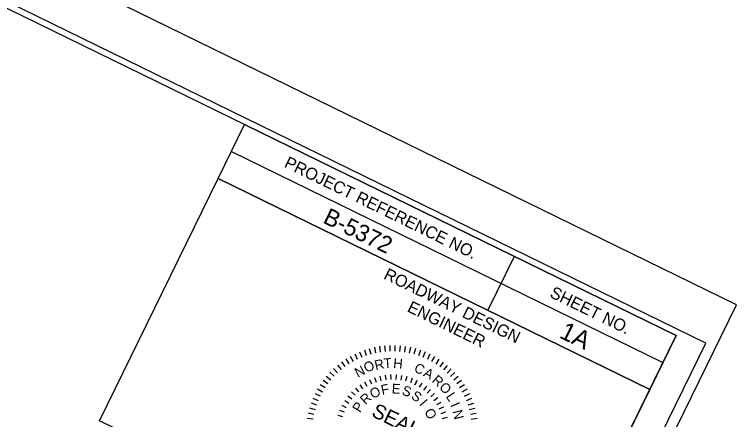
# Model space of a CAD drawing. Extents: x 1517888 to 1526099, y 633375 to 640181.
# Drawn here: x 1522517 to 1523118, y 635247 to 635585 of the extents above; entities that cross this region are included whole.
import ezdxf

# ---------------------------------------------------------------- set-up
doc = ezdxf.new("R2010")
doc.units = 0
for name, color, linetype in [('Default', 7, 'Continuous'), ('Sheet Cutting Line CELL', 7, 'Continuous'), ('Sheet Data Field CELL', 7, 'Continuous'), ('Sheet Plan CELL', 7, 'Continuous'), ('Sheet Plot Border Inside CELL', 7, 'Continuous'), ('Sheet Plot Border Outside CELL', 7, 'Continuous')]:
    doc.layers.add(name, color=color, linetype=linetype)

msp = doc.modelspace()

# ---------------------------------------------------------------- linework, layer by layer
at = {"layer": 'Default'}
for p, q in [((1522816.43, 635307.4), (1522817.44, 635302.63)), ((1522820.68, 635308.16), (1522821.4, 635303.34)), ((1522824.97, 635308.68), (1522825.4, 635303.82)), ((1522829.29, 635308.93), (1522829.42, 635304.05)), ((1522833.61, 635308.91), (1522833.44, 635304.04)), ((1522837.92, 635308.64), (1522837.47, 635303.78)), ((1522842.21, 635308.11), (1522841.46, 635303.29)), ((1522846.46, 635307.32), (1522845.42, 635302.56)), ((1522800.11, 635301.81), (1522802.24, 635297.43)), ((1522804.06, 635303.58), (1522805.91, 635299.07)), ((1522808.1, 635305.1), (1522809.68, 635300.49)), ((1522812.23, 635306.37), (1522813.53, 635301.67)), ((1522850.65, 635306.27), (1522849.33, 635301.58)), ((1522854.77, 635304.97), (1522853.17, 635300.37)), ((1522858.8, 635303.43), (1522856.92, 635298.93)), ((1522862.74, 635301.65), (1522860.6, 635297.27)), ((1522789.01, 635295.15), (1522791.9, 635291.21)), ((1522792.58, 635297.6), (1522795.21, 635293.49)), ((1522796.28, 635299.82), (1522798.66, 635295.57)), ((1522866.56, 635299.63), (1522864.16, 635295.39)), ((1522870.25, 635297.38), (1522867.6, 635293.3)), ((1522873.81, 635294.92), (1522870.91, 635291)), ((1522782.36, 635289.64), (1522785.7, 635286.07)), ((1522785.61, 635292.49), (1522788.72, 635288.74)), ((1522877.2, 635292.25), (1522874.07, 635288.51)), ((1522880.43, 635289.37), (1522877.08, 635285.82)), ((1522776.42, 635283.36), (1522780.17, 635280.23)), ((1522779.3, 635286.59), (1522782.85, 635283.24)), ((1522820.93, 635283.42), (1522821.82, 635279.45)), ((1522825.41, 635284.2), (1522825.91, 635280.16)), ((1522829.96, 635284.54), (1522830.07, 635280.49)), ((1522834.51, 635284.45), (1522834.23, 635280.4)), ((1522839.04, 635283.92), (1522838.36, 635279.91)), ((1522843.49, 635282.95), (1522842.43, 635279.02)), ((1522883.47, 635286.31), (1522879.91, 635282.98)), ((1522886.32, 635283.06), (1522882.58, 635279.95)), ((1522773.75, 635279.97), (1522777.67, 635277.07)), ((1522808.2, 635278.55), (1522810.19, 635275)), ((1522812.28, 635280.58), (1522813.92, 635276.86)), ((1522816.54, 635282.2), (1522817.81, 635278.34)), ((1522847.82, 635281.55), (1522846.4, 635277.75)), ((1522852.01, 635279.75), (1522850.22, 635276.1)), ((1522850.22, 635276.1), (1522852.01, 635279.75)), ((1522856, 635277.55), (1522853.87, 635274.09)), ((1522888.99, 635279.66), (1522885.05, 635276.78)), ((1522769.05, 635272.73), (1522773.29, 635270.32)), ((1522771.29, 635276.42), (1522775.38, 635273.76)), ((1522800.73, 635273.35), (1522803.36, 635270.25)), ((1522804.35, 635276.13), (1522806.66, 635272.79)), ((1522859.75, 635274.98), (1522857.3, 635271.74)), ((1522863.25, 635272.05), (1522860.49, 635269.06)), ((1522891.43, 635276.09), (1522887.33, 635273.46)), ((1522893.66, 635272.39), (1522889.4, 635270.01)), ((1522765.24, 635264.97), (1522769.74, 635263.09)), ((1522767.03, 635268.9), (1522771.41, 635266.76)), ((1522794.4, 635266.82), (1522797.58, 635264.28)), ((1522797.41, 635270.23), (1522800.33, 635267.41)), ((1522866.44, 635268.8), (1522863.41, 635266.09)), ((1522869.3, 635265.26), (1522866.03, 635262.86)), ((1522895.65, 635268.56), (1522891.27, 635266.44)), ((1522763.7, 635260.93), (1522768.3, 635259.33)), ((1522789.44, 635259.19), (1522793.04, 635257.31)), ((1522791.73, 635263.12), (1522795.14, 635260.91)), ((1522871.82, 635261.46), (1522868.32, 635259.38)), ((1522897.42, 635264.61), (1522892.91, 635262.76)), ((1522898.93, 635260.57), (1522894.32, 635258.99)), ((1522761.36, 635252.62), (1522766.12, 635251.58)), ((1522762.4, 635256.81), (1522767.09, 635255.49)), ((1522787.53, 635255.05), (1522791.3, 635253.53)), ((1522873.95, 635257.43), (1522870.26, 635255.7)), ((1522875.67, 635253.21), (1522871.84, 635251.85)), ((1522900.21, 635256.44), (1522895.51, 635255.15)), ((1522760.56, 635248.37), (1522765.39, 635247.62)), ((1522786.04, 635250.75), (1522789.93, 635249.6)), ((1522876.99, 635248.85), (1522873.05, 635247.87)), ((1522901.23, 635252.24), (1522896.47, 635251.23)), ((1522902, 635247.99), (1522897.18, 635247.27))]:
    msp.add_line(p, q, dxfattribs=at)
at = {"layer": 'Sheet Cutting Line CELL'}
msp.add_line((1523118.12, 635342.8), (1520093.48, 636822.08), dxfattribs=at)
at = {"layer": 'Sheet Plan CELL'}
for p, q in [((1522697.36, 635470.55), (1523056.78, 635294.76)), ((1522686.38, 635448.09), (1523045.79, 635272.3)), ((1522686.38, 635448.09), (1523045.79, 635272.3)), ((1522933.01, 635383.12), (1522911.04, 635338.21))]:
    msp.add_line(p, q, dxfattribs=at)
for points in [[(1523067.8, 635317.31), (1520372.85, 636635.35), (1519450.22, 634748.89), (1522145.17, 633430.84)], [(1522708.39, 635493.09), (1523067.8, 635317.31), (1523045.79, 635272.3), (1522686.38, 635448.09)], [(1522686.38, 635448.09), (1523045.79, 635272.3), (1522946.94, 635070.18), (1522587.52, 635245.97)], [(1522686.38, 635448.09), (1523045.79, 635272.3), (1522946.95, 635070.21), (1522587.53, 635245.99)]]:
    msp.add_lwpolyline(points, close=True, dxfattribs=at)
at = {"layer": 'Sheet Plot Border Inside CELL'}
msp.add_lwpolyline([(1519172.24, 634879.28), (1522165.43, 633415.37), (1523092.46, 635310.82), (1520099.27, 636774.73)], close=True, dxfattribs=at)
at = {"layer": 'Sheet Plot Border Outside CELL'}
msp.add_lwpolyline([(1519131.31, 634854.77), (1522155.94, 633375.48), (1523118.12, 635342.8), (1520093.48, 636822.08)], close=True, dxfattribs=at)

# ---------------------------------------------------------------- texts
at = {"layer": 'Default'}
for s, height, rotation, p in [('O', 8.12, 25.602, (1522809.89, 635285.92)), ('R', 8.12, 12.54527, (1522817.58, 635288.24)), ('T', 8.12, 4.38431, (1522824.48, 635289.92)), ('H', 8.12, 354.95236, (1522831.91, 635290.22)), ('N', 8.12, 27.56144, (1522802.68, 635281.82)), ('C', 8.12, 331.24167, (1522848.71, 635287.79)), ('A', 8.12, 331.24167, (1522856.61, 635283.74)), ('R', 8.12, 319.23237, (1522863.81, 635278.88)), ('F', 8.12, 12.12532, (1522822.9, 635267.68)), ('E', 8.12, 356.82908, (1522830.76, 635268.94)), ('O', 8.12, 316.17555, (1522869.84, 635273.32)), ('O', 8.12, 27.42157, (1522815.17, 635264.17)), ('S', 8.12, 341.53283, (1522838.83, 635268.09)), ('S', 8.12, 326.23659, (1522846.41, 635265.13)), ('R', 8.12, 42.71781, (1522809.07, 635259.04)), ('L', 8.12, 303.03927, (1522875.67, 635266.43)), ('P', 8.12, 58.01406, (1522804.43, 635252.35)), ('SEAL', 12.189, 333.88471, (1522813.26, 635250.31)), ('I', 8.12, 310.94034, (1522853.39, 635259.75)), ('I', 8.12, 293.4638, (1522879.47, 635259.32)), ('O', 8.12, 295.64409, (1522857.88, 635254.03)), ('N', 8.12, 284.16934, (1522881.44, 635254.09))]:
    msp.add_text(s, height=height, rotation=rotation, dxfattribs=at).set_placement(p)
at = {"layer": 'Sheet Data Field CELL'}
for s, height, p in [('B-5372', 14, (1522772.76, 635411.44)), ('1A ', 15, (1522969.67, 635315.77))]:
    msp.add_text(s, height=height, rotation=333.93772, dxfattribs=at).set_placement(p)
at = {"layer": 'Sheet Plan CELL'}
for s, height, p in [('PROJECT REFERENCE NO.', 10.0002, (1522740.63, 635457.96)), ('ROADWAY DESIGN', 10.0002, (1522823.4, 635364.82)), ('SHEET NO.', 10, (1522961.79, 635349.56)), ('ENGINEER', 10, (1522843.1, 635337.49))]:
    msp.add_text(s, height=height, rotation=333.93772, dxfattribs=at).set_placement(p)

doc.saveas('drawing.dxf')
